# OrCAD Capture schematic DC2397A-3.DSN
size Custom; title: DC / DC CONVERTER WITH 1.6uA QUIESCENT CURRENT; rev: 3; note: DEMO CIRCUIT 2397A
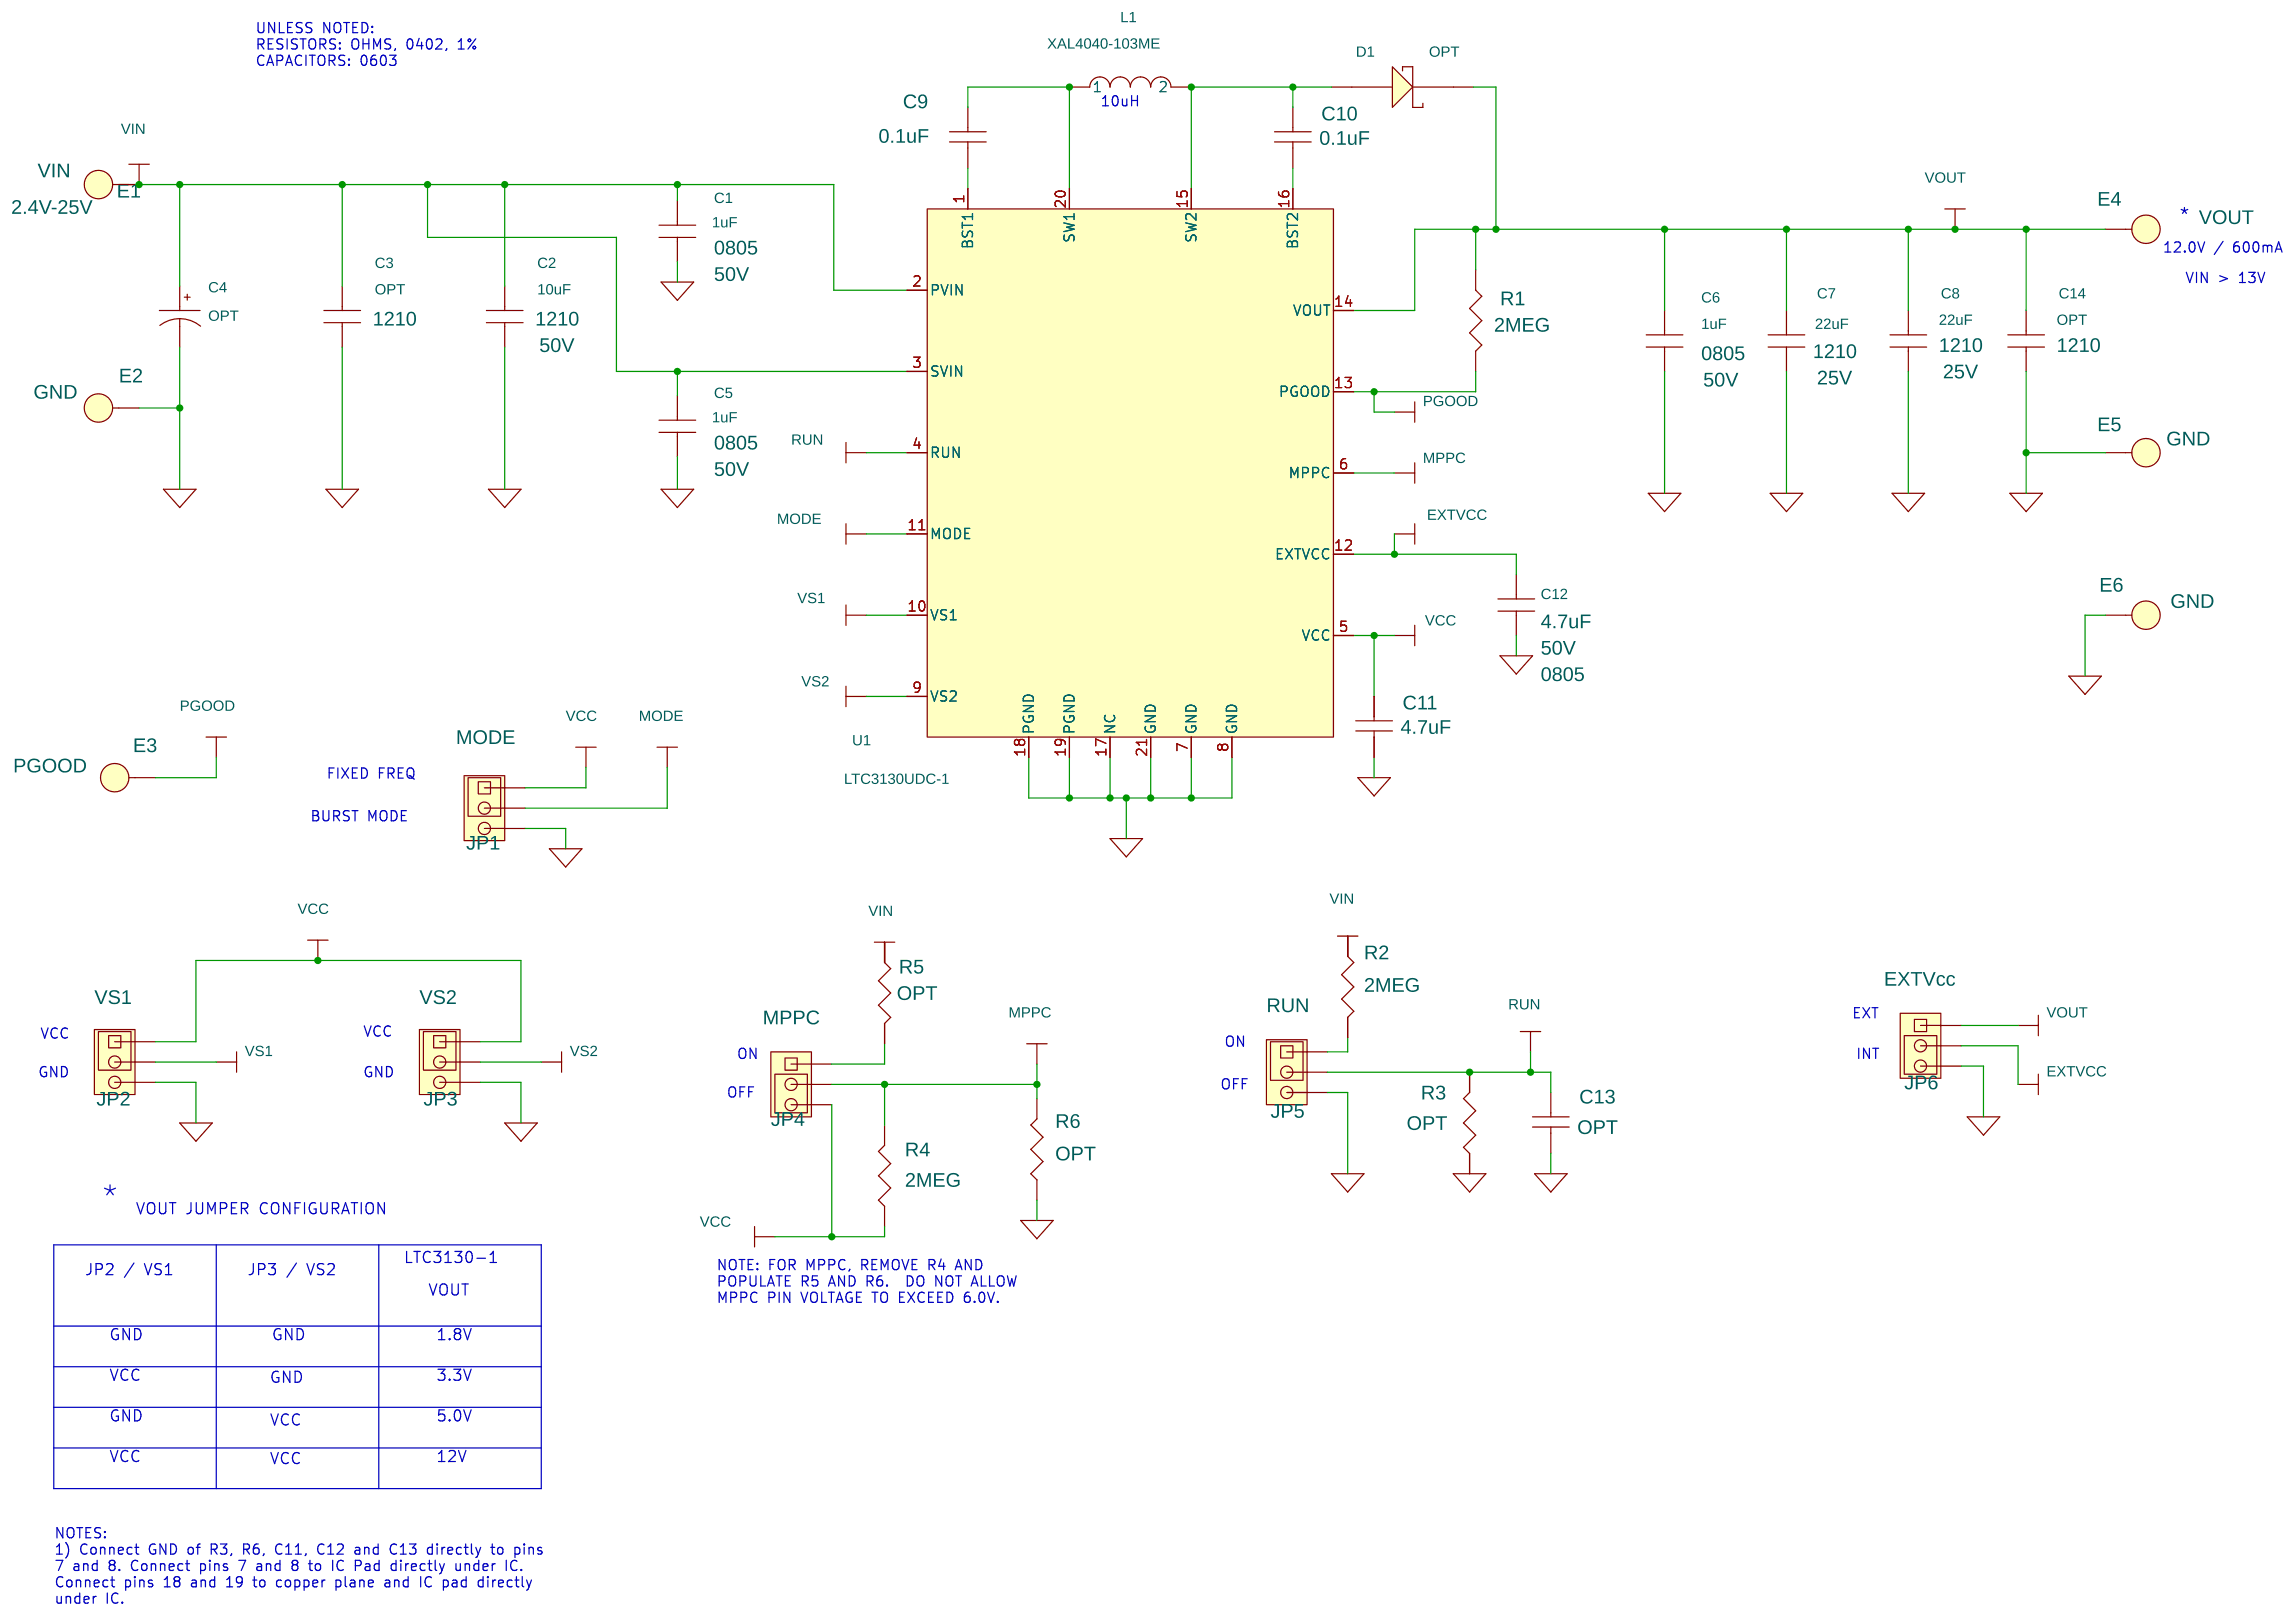
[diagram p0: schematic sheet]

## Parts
C1  1uF  [0805]
C2  10uF  [1210]
C3  OPT  [1210]
C4  OPT  [CAP-EEE-FP1V221AP]
C5  1uF  [0805]
C6  1uF  [0805]
C7  22uF  [1210]
C8  22uF  [1210]
C9  0.1uF  [0603]
C10  0.1uF  [0603]
C11  4.7uF  [0603]
C12  4.7uF  [0805]
C13  OPT  [0603]
C14  OPT  [1210]
D1  OPT  [SOD-123]
E1  0.09"  [MILL-MAX-2501-2]
E2  0.09"  [MILL-MAX-2501-2]
E3  0.09"  [MILL-MAX-2501-2]
E4  0.09"  [MILL-MAX-2501-2]
E5  0.09"  [MILL-MAX-2501-2]
E6  0.09"  [MILL-MAX-2501-2]
JP1  HD1X3-079  [HD1X3-079]
JP2  HD1X3-079  [HD1X3-079]
JP3  HD1X3-079  [HD1X3-079]
JP4  HD1X3-079  [HD1X3-079]
JP5  HD1X3-079  [HD1X3-079]
JP6  HD1X3-079  [HD1X3-079]
L1  XAL4040-103ME  [IND-XAL40XX]
R1  2MEG  [0402-SMALL]
R2  2MEG  [0402-SMALL]
R3  OPT  [0402-SMALL]
R4  2MEG  [0402-SMALL]
R5  OPT  [0402-SMALL]
R6  OPT  [0402-SMALL]
U1  LTC3130UDC-1  [LTC-UDC-20-1742]

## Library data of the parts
C1 = Capacitor_0805_1: Voltage: 50V
C2 = Capacitor_1210_1: Voltage: 50V
C3 = Capacitor_1210_4: Voltage: 25V
C4 = Capacitor_EEE-FP1V221AP_0
C5 = Capacitor_0805_2: Voltage: 50V
C6 = Capacitor_0805: Voltage: 50V
C7 = Capacitor_1210: Voltage: 25V
C8 = Capacitor_1210_3: Voltage: 25V
C9-C11 = JMK107BJ105KA-T
C12 = Capacitor_0805_3: Voltage: 50V
C13 = JMK107BJ105KA-T: 1st Part Field: 50V
C14 = Capacitor_1210_2: Voltage: 25V
D1 = SCHOTTKY_SOD123_1
E1 = E_2: COMPFIXED: VIN; COMPGROUP: 2.4V-25V
E2 E5 E6 = E_2: COMPFIXED: GND
E3 = E_2: COMPFIXED: PGOOD; COMPGROUP: 2.35V-25V
E4 = E_2: 1A peak: 1A peak; COMPFIXED: VOUT; COMPGROUP: 5.0V / 600mA
JP1 = HD1X3_1: silkscreen: MODE
JP2 = HD1X3_1: silkscreen: VS1
JP3 = HD1X3_2: silkscreen: VS2
JP4 = HD1X3_0: silkscreen: MPPC
JP5 = HD1X3_1: silkscreen: RUN
JP6 = HD1X3_3: silkscreen: EXTVcc
L1 = Coilcraft_XAL4040
R1 R5 R6 = CR05-153JM
R2-R4 = CR05-105JM
U1 = LTC3130-1-UDC

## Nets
GND: C1.2 C2.2 C3.2 C4.2(-) C5.2 C6.2 C7.2 C8.2 C11.2 C12.2 C13.2 C14.2 E2.1(A) E5.1(A) E6.1(A) JP1.3 JP2.3 JP3.3 JP5.3 JP6.3 R3.1 R6.1 U1.7(GND) U1.8(GND) U1.17(NC) U1.18(PGND) U1.19(PGND) U1.21(GND)
VCC: C11.1 JP1.1 JP2.1 JP3.1 JP4.3 R4.1 U1.5(VCC)
VIN: C1.1 C2.1 C3.1 C4.1(+) C5.1 E1.1(A) R2.1 R5.1 U1.2(PVIN) U1.3(SVIN)
EXTVcc: C12.1 JP6.2 U1.12(EXTVCC)
MODE: JP1.2 U1.11(MODE)
MPPC: JP4.2 R4.2 R6.2 U1.6(MPPC)
PGOOD: E3.1(A) R1.2 U1.13(PGOOD)
RUN: C13.1 JP5.2 R3.2 U1.4(RUN)
VOUT: C6.1 C7.1 C8.1 C14.1 D1.1(C) E4.1(A) JP6.1 R1.1 U1.14(VOUT)
VS1: JP2.2 U1.10(VS1)
VS2: JP3.2 U1.9(VS2)
N16654302: C10.1 D1.2(A) L1.2 U1.15(SW2)
N16666361: C9.1 L1.1 U1.20(SW1)
N17074027: C9.2 U1.1(BST1)
N17074184: C10.2 U1.16(BST2)
N17080962: JP5.1 R2.2
N17081290: JP4.1 R5.2

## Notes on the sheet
- UNLESS NOTED:
  RESISTORS: OHMS, 0402, 1%
  CAPACITORS: 0603
- 10uH
- *
- 12.0V / 600mA
- VIN > 13V
- FIXED FREQ
- BURST MODE
- EXT
- VCC
- VCC
- ON
- GND
- GND
- ON
- INT
- OFF
- OFF
- *
- VOUT JUMPER CONFIGURATION
- LTC3130-1
- NOTE: FOR MPPC, REMOVE R4 AND
  POPULATE R5 AND R6.  DO NOT ALLOW
  MPPC PIN VOLTAGE TO EXCEED 6.0V.
- JP2 / VS1
- JP3 / VS2
- VOUT
- GND
- GND
- 1.8V
- VCC
- GND
- 3.3V
- GND
- VCC
- 5.0V
- VCC
- VCC
- 12V
- NOTES:
  1) Connect GND of R3, R6, C11, C12 and C13 directly to pins
  7 and 8. Connect pins 7 and 8 to IC Pad directly under IC.
  Connect pins 18 and 19 to copper plane and IC pad directly
  under IC.
